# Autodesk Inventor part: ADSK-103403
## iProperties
Shininess: 21.0
Created: 2001-04
Part Number: ADSK-103403
Document SubType Name: Modeling
Designer: Administrator
Stock Number: ADSK-103403
Density: 1 g/cm^3
Density: 0.0
Volumn: 0.0
Area: 0.0
PropertySet Name: Model Information
Control State: 0
Master: False
Checked Out: False
Author: Administrator
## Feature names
1. Revolution1
2. Chamfer1
3. Hole1
4. Hole3
5. Fillet1
6. Circular Pattern1
